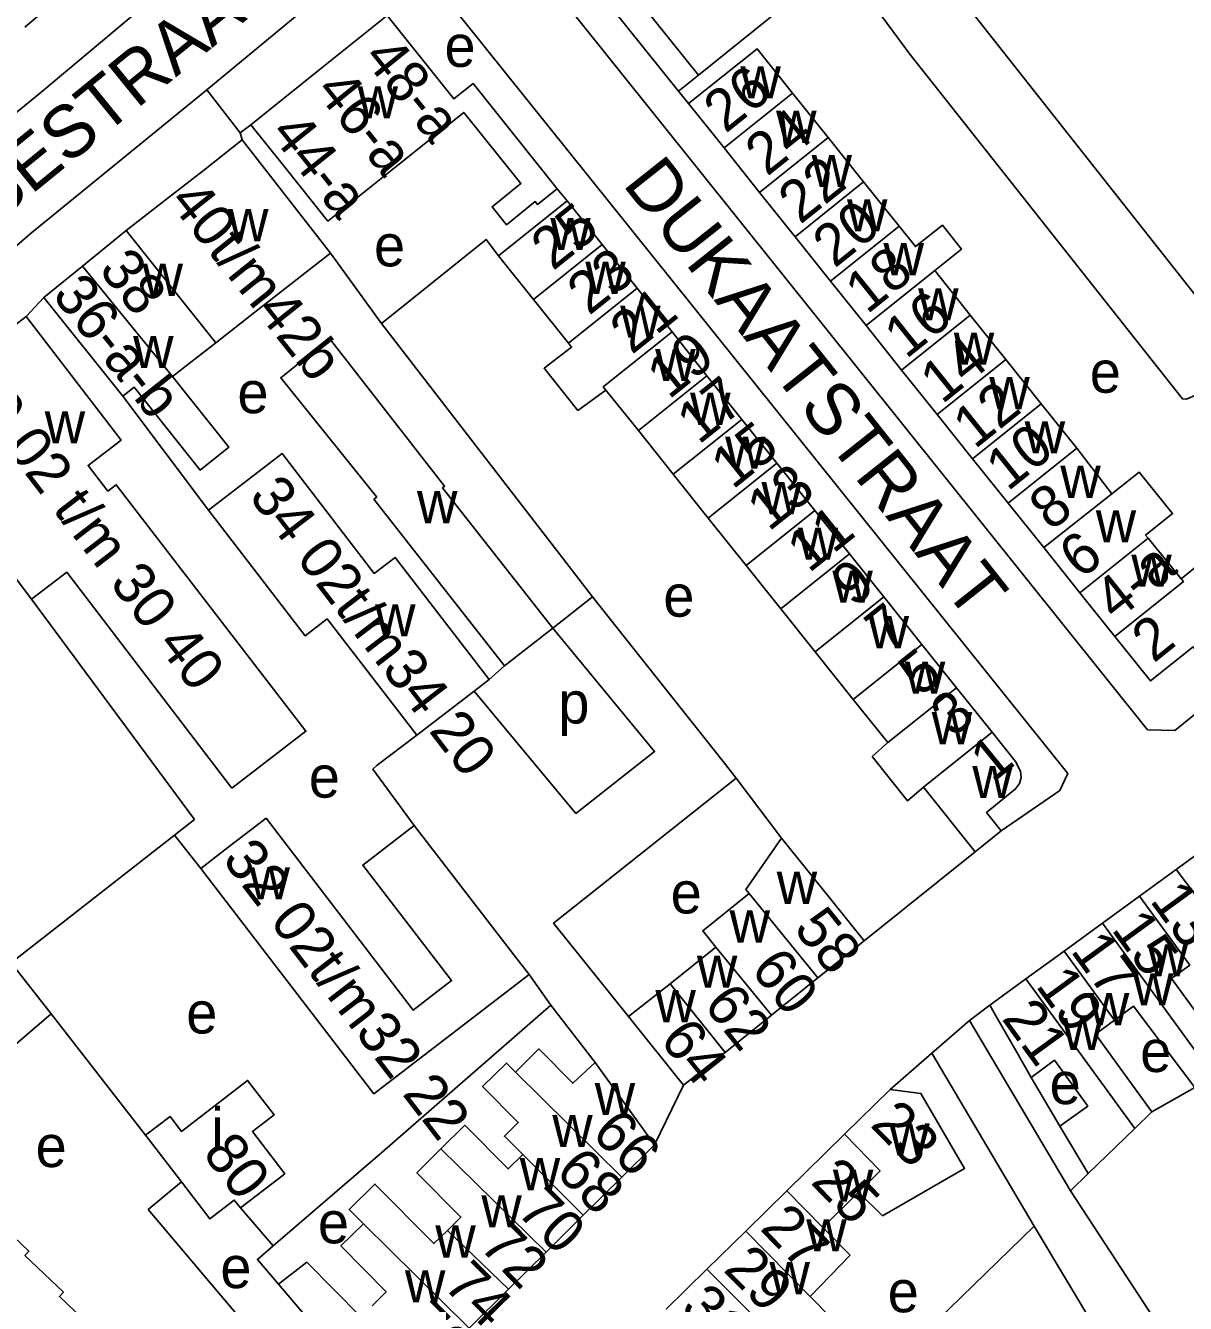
# Model space of a CAD drawing. Extents: x 161141 to 163125, y 381621 to 383200.
# Drawn here: x 162034.5 to 162145.3, y 382848.2 to 382970.4 of the extents above; entities that cross this region are included whole.
import ezdxf

# ---------------------------------------------------------------- set-up
doc = ezdxf.new("R2010")
doc.units = 0
for name, color, linetype in [('BLT_Basislijn', 7, 'Continuous'), ('BLT_Bebouwing', 7, 'Continuous'), ('BLT_Centroide', 7, 'Continuous'), ('BLT_Huisnummer', 7, 'Continuous'), ('BLT_Huisnummer_ tussenligend', 7, 'Continuous'), ('BLT_Huisnummer_reeks', 7, 'Continuous'), ('BLT_Onderverdeling_panden', 7, 'Continuous'), ('BLT_Plantopo', 7, 'Continuous'), ('BLT_Straatnaam', 7, 'Continuous')]:
    doc.layers.add(name, color=color, linetype=linetype)

msp = doc.modelspace()

# ---------------------------------------------------------------- linework, layer by layer
at = {"layer": 'BLT_Basislijn'}
for p, q in [((162098.79, 382965.63), (162112.37, 382976.59)), ((162039.04, 382974.17), (162034.4, 382970.22)), ((162054.96, 382960.11), (162051.8, 382964.24)), ((162096.87, 382964.1), (162097.83, 382962.92)), ((162055.99, 382960.89), (162054.96, 382960.11)), ((162055.17, 382959.44), (162054.96, 382960.11)), ((162086.24, 382953.62), (162085.29, 382954.77)), ((162063.62, 382948.61), (162068.5, 382941.89)), ((162036.21, 382944.38), (162034.52, 382942.57)), ((162043.75, 382934.93), (162051.96, 382924.05)), ((162035.04, 382915.55), (162050.62, 382894.48)), ((162084.88, 382912.76), (162088.66, 382915.76)), ((162078.77, 382907.84), (162080.25, 382909.15)), ((162068.06, 382899.66), (162071.85, 382902.52)), ((162134.11, 382898.87), (162133.32, 382897.23)), ((162102.38, 382898.42), (162084.92, 382884.56)), ((162102.38, 382898.42), (162106.74, 382892.7)), ((162133.32, 382897.23), (162127.73, 382893.39)), ((162051.2, 382889.78), (162048.7, 382892.97)), ((162084.92, 382884.56), (162092.09, 382875.64)), ((162082.59, 382879.65), (162084.68, 382876.73)), ((162088.9, 382871.25), (162084.68, 382876.73)), ((162126.65, 382876.72), (162124.71, 382875.24)), ((162036.9, 382875.89), (162011.67, 382854.3)), ((162045.92, 382864.28), (162036.9, 382875.89)), ((162124.71, 382875.24), (162121.11, 382872.13)), ((162124.71, 382875.24), (162134.35, 382858.98)), ((162121.11, 382872.13), (162117.1, 382868.65)), ((162121.11, 382872.13), (162130.87, 382855.59)), ((162133.34, 382865.14), (162130.59, 382869.82)), ((162146.25, 382868.84), (162142.14, 382866.53)), ((162058.13, 382853.71), (162068.33, 382862.47)), ((162134.35, 382858.98), (162136.04, 382860.62)), ((162049.35, 382859.82), (162046.17, 382857.17)), ((162143.03, 382845.71), (162134.35, 382858.98)), ((162057.64, 382843.63), (162046.17, 382857.17)), ((162054.99, 382857.34), (162058.13, 382853.71)), ((162116.71, 382841.81), (162130.87, 382855.59)), ((162130.87, 382855.59), (162139.06, 382841.97))]:
    msp.add_line(p, q, dxfattribs=at)
for points in [[(162055.07, 383020.8), (162073.06, 382998.55), (162074.21, 382996.11), (162061.33, 382985.3), (162036.1, 382964.14), (162021.9, 382952.54)], [(162078.89, 382986.26), (162079.12, 382981.19), (162141.72, 382903.05), (162144.33, 382902.98), (162163.54, 382918.51)], [(162119.35, 382978.75), (162148.02, 382942.41), (162160.41, 382952.54)], [(162067.43, 382977.19), (162051.8, 382964.24)], [(162134.11, 382898.87), (162072.44, 382975.73), (162067.43, 382977.19)], [(162148.78, 382936.95), (162148.4, 382936.64), (162146.31, 382935.04), (162145.46, 382934.64), (162145.05, 382934.68), (162119.01, 382967.64), (162114.01, 382974.38)], [(162051.8, 382964.24), (162051.59, 382964.07), (162034.86, 382950.43), (162030.3, 382946.48), (162029.11, 382945.73), (162022.92, 382940.82), (162016.17, 382934.9), (162011.73, 382931.63), (162000.21, 382922), (161995.04, 382917.92), (161994.27, 382917.07), (161980.96, 382906.53), (161973.3, 382900), (161972.62, 382899.42), (161974.49, 382896.95)], [(162068.5, 382941.89), (162078.49, 382949.92), (162079.67, 382948.37)], [(162088.66, 382915.76), (162088.34, 382916.16), (162086.1, 382919.08), (162068.5, 382941.89)], [(162102.38, 382898.42), (162101.15, 382900), (162088.66, 382915.76)], [(162077.34, 382906.74), (162087.07, 382895.05), (162094.6, 382900.97), (162084.88, 382912.76)], [(162071.61, 382893.9), (162067.65, 382899.28), (162068.06, 382899.66)], [(162048.7, 382892.97), (162050.62, 382894.48)], [(162036.9, 382875.89), (162033.07, 382880.77), (162048.7, 382892.97)], [(162068.33, 382862.47), (162068.56, 382862.67), (162084.68, 382876.73)], [(162094.57, 382863.38), (162097.36, 382869.08)], [(162058.65, 382850.06), (162056.62, 382852.41), (162058.13, 382853.71)]]:
    msp.add_lwpolyline(points, dxfattribs=at)
at = {"layer": 'BLT_Bebouwing'}
for p, q in [((162111.18, 382959.67), (162107.79, 382963.92)), ((162114.58, 382955.43), (162111.18, 382959.67)), ((162104.62, 382954.42), (162101.23, 382958.67)), ((162117.98, 382951.18), (162114.58, 382955.43)), ((162044.07, 382950.78), (162047.52, 382953.47)), ((162086.24, 382953.62), (162079.67, 382948.37)), ((162089.58, 382949.44), (162086.24, 382953.62)), ((162108.02, 382950.18), (162104.62, 382954.42)), ((162039.89, 382947.37), (162044.07, 382950.78)), ((162111.42, 382945.93), (162108.02, 382950.18)), ((162092.92, 382945.26), (162089.58, 382949.44)), ((162036.21, 382944.38), (162039.89, 382947.37)), ((162083.01, 382944.19), (162079.67, 382948.37)), ((162124.77, 382942.69), (162121.37, 382946.94)), ((162096.26, 382941.08), (162092.92, 382945.26)), ((162114.81, 382941.69), (162111.42, 382945.93)), ((162043.75, 382934.93), (162036.21, 382944.38)), ((162086.35, 382940.01), (162083.01, 382944.19)), ((162024.72, 382935.01), (162034.52, 382942.57)), ((162128.17, 382938.45), (162124.77, 382942.69)), ((162118.21, 382937.44), (162114.81, 382941.69)), ((162099.6, 382936.9), (162096.26, 382941.08)), ((162131.56, 382934.2), (162128.17, 382938.45)), ((162102.95, 382932.72), (162099.6, 382936.9)), ((162121.61, 382933.2), (162118.21, 382937.44)), ((162093.04, 382931.65), (162089.93, 382935.52)), ((162134.96, 382929.96), (162131.56, 382934.2)), ((162106.29, 382928.54), (162102.95, 382932.72)), ((162125, 382928.95), (162121.61, 382933.2)), ((162096.38, 382927.47), (162093.04, 382931.65)), ((162138.32, 382925.61), (162134.96, 382929.96)), ((162109.91, 382924.01), (162106.29, 382928.54)), ((162128.4, 382924.71), (162125, 382928.95)), ((162099.72, 382923.29), (162096.38, 382927.47)), ((162067.76, 382925.08), (162080.25, 382909.15)), ((162131.8, 382920.46), (162128.4, 382924.71)), ((162103.34, 382918.76), (162099.72, 382923.29)), ((162113.22, 382919.88), (162109.91, 382924.01)), ((162135.25, 382916.15), (162131.8, 382920.46)), ((162144.94, 382917.48), (162141.77, 382921.36)), ((162116.51, 382915.76), (162113.22, 382919.88)), ((162106.65, 382914.62), (162103.34, 382918.76)), ((162033.36, 382917.72), (162035.04, 382915.55)), ((162120.15, 382911.2), (162116.51, 382915.76)), ((162138.59, 382911.97), (162135.25, 382916.15)), ((162109.95, 382910.5), (162106.65, 382914.62)), ((162123.46, 382907.07), (162120.15, 382911.2)), ((162113.59, 382905.95), (162109.95, 382910.5)), ((162077.34, 382906.74), (162078.77, 382907.84)), ((162126.87, 382902.81), (162123.46, 382907.07)), ((162071.85, 382902.52), (162077.34, 382906.74)), ((162116.89, 382901.82), (162113.59, 382905.95)), ((162115.4, 382900.49), (162116.89, 382901.82)), ((162125.25, 382891.39), (162120.3, 382897.56)), ((162081.13, 382881.54), (162071.61, 382893.9)), ((162125.25, 382891.39), (162127.73, 382893.39)), ((162148.2, 382892.43), (162144.46, 382889.7)), ((162053.39, 382891.47), (162051.2, 382889.78)), ((162114.64, 382882.88), (162125.25, 382891.39)), ((162144.46, 382889.7), (162140.94, 382887.14)), ((162140.94, 382887.14), (162137.4, 382884.56)), ((162137.4, 382884.56), (162133.74, 382881.89)), ((162114.64, 382882.88), (162110.21, 382879.32)), ((162082.59, 382879.65), (162081.13, 382881.54)), ((162100.44, 382882.28), (162096.07, 382878.77)), ((162133.74, 382881.89), (162130.09, 382879.23)), ((162110.21, 382879.32), (162105.77, 382875.76)), ((162096.07, 382878.77), (162092.09, 382875.64)), ((162105.77, 382875.76), (162101.34, 382872.21)), ((162101.34, 382872.21), (162097.36, 382869.08)), ((162117.1, 382868.65), (162112.76, 382864.4)), ((162142.14, 382866.53), (162140.5, 382864.94)), ((162112.76, 382864.4), (162107.23, 382858.98)), ((162091.46, 382860.29), (162094.57, 382863.38)), ((162087.76, 382856.63), (162091.46, 382860.29)), ((162107.23, 382858.98), (162103.32, 382855.12)), ((162110.67, 382855.48), (162114.09, 382858.84)), ((162084.22, 382853.12), (162087.76, 382856.63)), ((162103.32, 382855.12), (162099.59, 382851.47)), ((162080.64, 382849.58), (162084.22, 382853.12)), ((162099.59, 382851.47), (162095.7, 382847.65)), ((162076.86, 382845.83), (162080.64, 382849.58))]:
    msp.add_line(p, q, dxfattribs=at)
for points in [[(162090.84, 382988.77), (162084.33, 382983.57), (162090.64, 382975.62), (162088.83, 382974.16), (162096.87, 382964.1)], [(162098.2, 382979.54), (162091.76, 382974.41), (162098.79, 382965.63)], [(162085.29, 382954.77), (162077.24, 382964.82), (162075.4, 382963.38), (162069.02, 382971.32), (162062.5, 382966.11)], [(162097.83, 382962.92), (162104.39, 382968.16), (162107.79, 382963.92)], [(162062.5, 382966.11), (162055.99, 382960.89)], [(162096.87, 382964.1), (162098.79, 382965.63)], [(162085.29, 382954.77), (162083.41, 382953.26), (162083.19, 382953.54), (162080.43, 382951.33), (162079.05, 382953.05), (162081.81, 382955.26), (162076.35, 382962.07), (162069.88, 382956.89)], [(162101.23, 382958.67), (162097.83, 382962.92)], [(162055.99, 382960.89), (162059.12, 382956.99), (162063.37, 382951.68), (162069.88, 382956.89)], [(162047.52, 382953.47), (162051.46, 382956.51), (162055.17, 382959.44)], [(162055.17, 382959.44), (162063.62, 382948.61)], [(162121.37, 382946.94), (162123.95, 382949), (162122.11, 382951.3), (162119.53, 382949.24), (162117.98, 382951.18)], [(162056.1, 382942.74), (162063.62, 382948.61)], [(162034.52, 382942.57), (162043.59, 382930.74), (162040.44, 382928.32), (162042.33, 382925.86), (162043.12, 382926.47), (162061.26, 382902.9), (162054.18, 382897.48), (162038.39, 382918.11), (162035.04, 382915.55)], [(162052.64, 382940.04), (162056.1, 382942.74)], [(162048.51, 382936.82), (162050.4, 382938.3), (162052.64, 382940.04)], [(162084.88, 382912.76), (162074.33, 382926.18), (162074.52, 382926.33), (162063.52, 382940.46), (162058.85, 382936.7), (162068.03, 382925.29), (162067.76, 382925.08)], [(162089.93, 382935.52), (162087.26, 382933.58), (162084.03, 382937.61), (162086.65, 382939.62), (162086.35, 382940.01)], [(162048.51, 382936.82), (162053.9, 382930.08), (162051.14, 382927.88), (162044.83, 382935.79), (162043.75, 382934.93)], [(162051.96, 382924.05), (162058.99, 382929.46), (162067.79, 382918), (162069.78, 382919.53), (162078.77, 382907.84)], [(162141.77, 382921.36), (162141.53, 382921.66), (162144.11, 382923.72), (162140.91, 382927.68), (162138.32, 382925.61)], [(162051.96, 382924.05), (162061.18, 382912.04), (162063.28, 382913.65), (162071.85, 382902.52)], [(162151.55, 382912.48), (162146.48, 382918.73), (162144.94, 382917.48)], [(162080.25, 382909.15), (162084.88, 382912.76)], [(162151.55, 382912.48), (162147.49, 382909.24), (162146.07, 382910.99), (162141.99, 382907.72), (162138.59, 382911.97)], [(162127.73, 382893.39), (162126.33, 382895.13), (162129.1, 382897.39), (162129.47, 382897.91), (162129.64, 382898.48), (162129.59, 382899.08), (162129.11, 382900), (162126.87, 382902.81)], [(162120.3, 382897.56), (162118.76, 382896.27), (162115.4, 382900.49)], [(162071.61, 382893.9), (162066.69, 382890.12), (162075.19, 382879.07), (162071.52, 382876.24), (162057.45, 382894.59), (162053.39, 382891.47)], [(162106.74, 382892.7), (162103.33, 382887.77), (162103.62, 382887.41)], [(162114.64, 382882.88), (162111.51, 382886.77), (162106.74, 382892.7)], [(162051.2, 382889.78), (162067.76, 382868.23), (162082.59, 382879.65)], [(162103.62, 382887.41), (162099.19, 382883.84), (162100.44, 382882.28)], [(162149.39, 382871.89), (162144.02, 382879.26), (162145.76, 382880.53)], [(162130.09, 382879.23), (162126.65, 382876.72), (162127.23, 382875.71)], [(162138.56, 382875.28), (162140.39, 382876.61), (162146.25, 382868.84)], [(162092.09, 382875.64), (162097.36, 382869.08)], [(162127.23, 382875.71), (162129.12, 382872.38), (162130.59, 382869.82)], [(162142.14, 382866.53), (162136.74, 382873.95), (162138.56, 382875.28)], [(162088.9, 382871.25), (162086.77, 382869.26), (162083.54, 382872.54), (162081.29, 382870.31)], [(162081.29, 382870.31), (162080.43, 382871.19), (162078.15, 382868.94), (162081.56, 382865.5), (162080.24, 382864.19), (162081.99, 382862.43)], [(162094.57, 382863.38), (162088.9, 382871.25)], [(162130.59, 382869.82), (162132.82, 382871.45), (162136, 382867.08), (162133.34, 382865.14)], [(162054.99, 382857.34), (162058.96, 382860.38), (162059.24, 382860.6), (162056.14, 382864.63), (162058.23, 382866.24), (162055.69, 382869.53), (162049.38, 382864.65), (162048.27, 382866.09), (162045.92, 382864.28)], [(162116.37, 382856.57), (162124.23, 382861.12), (162120.06, 382868.27), (162117.1, 382868.65)], [(162045.92, 382864.28), (162046.26, 382863.83), (162049.35, 382859.82)], [(162081.99, 382862.43), (162080.6, 382861.06), (162076.46, 382865.24), (162074.17, 382862.97)], [(162136.04, 382860.62), (162133.34, 382865.14)], [(162140.5, 382864.94), (162136.04, 382860.62)], [(162074.17, 382862.97), (162071.87, 382860.7), (162076.07, 382856.46), (162074.79, 382855.19)], [(162049.35, 382859.82), (162052.06, 382856.29), (162054.41, 382858.09), (162054.99, 382857.34)], [(162074.79, 382855.19), (162073.5, 382853.92), (162067.86, 382859.62), (162065.4, 382857.19), (162066.75, 382855.82)], [(162114.09, 382858.84), (162116.37, 382856.57)], [(162066.75, 382855.82), (162064.6, 382853.7), (162068.92, 382849.32), (162067.58, 382847.99)], [(162109.46, 382848.87), (162113.29, 382852.81), (162110.67, 382855.48)], [(162066.5, 382846.93), (162061.34, 382852.15), (162058.65, 382850.06)], [(162058.65, 382850.06), (162063.67, 382844.12), (162062.78, 382843.24), (162067.09, 382838.18), (162069.12, 382838.17)], [(162110.34, 382844.31), (162111.55, 382843.08), (162113.38, 382844.89), (162109.46, 382848.87)]]:
    msp.add_lwpolyline(points, dxfattribs=at)
at = {"layer": 'BLT_Onderverdeling_panden'}
for p, q in [((162101.23, 382958.67), (162107.79, 382963.92)), ((162104.62, 382954.42), (162111.18, 382959.67)), ((162108.02, 382950.18), (162114.58, 382955.43)), ((162111.42, 382945.93), (162117.98, 382951.18)), ((162052.64, 382940.04), (162044.07, 382950.78)), ((162083.01, 382944.19), (162089.58, 382949.44)), ((162048.51, 382936.82), (162039.89, 382947.37)), ((162114.81, 382941.69), (162121.37, 382946.94)), ((162086.35, 382940.01), (162092.92, 382945.26)), ((162118.21, 382937.44), (162124.77, 382942.69)), ((162121.61, 382933.2), (162128.17, 382938.45)), ((162093.04, 382931.65), (162099.6, 382936.9)), ((162125, 382928.95), (162131.56, 382934.2)), ((162096.38, 382927.47), (162102.95, 382932.72)), ((162128.4, 382924.71), (162134.96, 382929.96)), ((162099.72, 382923.29), (162106.29, 382928.54)), ((162131.8, 382920.46), (162138.32, 382925.61)), ((162103.34, 382918.76), (162109.91, 382924.01)), ((162135.25, 382916.15), (162141.77, 382921.36)), ((162106.65, 382914.62), (162113.22, 382919.88)), ((162109.95, 382910.5), (162116.51, 382915.76)), ((162113.59, 382905.95), (162120.15, 382911.2)), ((162116.89, 382901.82), (162123.46, 382907.07)), ((162126.87, 382902.81), (162120.3, 382897.56)), ((162152.57, 382878.9), (162144.46, 382889.7)), ((162110.21, 382879.32), (162103.62, 382887.41)), ((162145.76, 382880.53), (162140.94, 382887.14)), ((162147.77, 382870.32), (162137.4, 382884.56)), ((162105.77, 382875.76), (162100.44, 382882.28)), ((162138.56, 382875.28), (162133.74, 382881.89)), ((162140.5, 382864.94), (162130.09, 382879.23)), ((162096.07, 382878.77), (162101.34, 382872.21)), ((162081.29, 382870.31), (162091.46, 382860.29)), ((162074.17, 382862.97), (162084.22, 382853.12)), ((162081.99, 382862.43), (162087.76, 382856.63)), ((162110.67, 382855.48), (162107.23, 382858.98)), ((162066.75, 382855.82), (162076.86, 382845.83)), ((162074.79, 382855.19), (162080.64, 382849.58)), ((162109.46, 382848.87), (162103.32, 382855.12)), ((162108.5, 382842.6), (162099.59, 382851.47))]:
    msp.add_line(p, q, dxfattribs=at)
for points in [[(162089.93, 382935.52), (162089.69, 382935.83), (162096.26, 382941.08)], [(162138.59, 382911.97), (162145.15, 382917.22), (162144.94, 382917.48)], [(162114.09, 382858.84), (162116.15, 382860.87), (162112.76, 382864.4)]]:
    msp.add_lwpolyline(points, dxfattribs=at)
at = {"layer": 'BLT_Plantopo'}
msp.add_lwpolyline([(162021.72, 382847.94), (162018.1, 382851.46), (162014.52, 382847.57), (162009.98, 382852.51), (162023.22, 382864.65), (162027.18, 382860.7), (162027.47, 382860.94), (162031.61, 382857.01), (162031.2, 382856.58), (162034.77, 382853.19), (162034.39, 382852.78), (162038.08, 382849.28), (162037.69, 382848.87), (162041.31, 382845.43)], dxfattribs=at)

# ---------------------------------------------------------------- texts
at = {"layer": 'BLT_Centroide'}
for s, p in [('e', (162074.51, 382966.42)), ('w', (162102.8, 382963.41)), ('w', (162066.2, 382961.5)), ('w', (162106.21, 382959.16)), ('w', (162109.6, 382954.94)), ('w', (162112.99, 382950.69)), ('w', (162053.81, 382949.75)), ('w', (162084.62, 382948.91)), ('e', (162067.77, 382947.35)), ('w', (162116.48, 382946.5)), ('w', (162045.64, 382944.53)), ('w', (162087.97, 382944.72)), ('w', (162119.79, 382942.19)), ('w', (162091.3, 382940.53)), ('w', (162044.74, 382937.62)), ('w', (162123.2, 382937.94)), ('w', (162094.65, 382936.38)), ('e', (162136.2, 382935.27)), ('e', (162054.71, 382933.31)), ('w', (162126.59, 382933.69)), ('w', (162097.99, 382932.19)), ('w', (162036.29, 382930.42)), ('w', (162129.98, 382929.47)), ('w', (162101.34, 382928)), ('w', (162133.38, 382925.22)), ('w', (162104.81, 382923.66)), ('w', (162071.88, 382922.8)), ('w', (162136.77, 382920.97)), ('w', (162108.28, 382919.31)), ('w', (162140.17, 382916.72)), ('w', (162111.59, 382915.19)), ('e', (162095.43, 382913.86)), ('w', (162067.87, 382911.97)), ('w', (162115.05, 382910.84)), ('w', (162118.52, 382906.5)), ('p', (162085.39, 382903.65)), ('w', (162121.09, 382901.66)), ('e', (162061.54, 382896.56)), ('w', (162124.97, 382896.52)), ('w', (162055.87, 382886.83)), ('w', (162106.27, 382886.4)), ('e', (162096.13, 382885.49)), ('w', (162101.76, 382882.7)), ('w', (162098.64, 382878.38)), ('w', (162141.72, 382879.48)), ('w', (162140.33, 382876.69)), ('w', (162094.67, 382875.09)), ('w', (162136.11, 382874.8)), ('e', (162049.82, 382874.01)), ('w', (162133.58, 382872.42)), ('e', (162141.02, 382870.33)), ('e', (162132.36, 382867.26)), ('w', (162088.87, 382866.22)), ('i', (162052.22, 382862.91)), ('w', (162084.81, 382863.16)), ('e', (162035.42, 382861.24)), ('w', (162117.03, 382862.34)), ('w', (162081.7, 382859.03)), ('w', (162111.64, 382857.92)), ('w', (162078.03, 382855.48)), ('e', (162062.41, 382853.95)), ('w', (162109.09, 382853.17)), ('w', (162073.63, 382852.59)), ('e', (162053.08, 382849.67)), ('w', (162105.58, 382849.09)), ('w', (162070.73, 382848.3)), ('e', (162116.88, 382847.36))]:
    msp.add_text(s, height=4, dxfattribs=at).set_placement(p)
at = {"layer": 'BLT_Huisnummer'}
for s, rotation, p in [('24', 38.663, (162105.34, 382955.89)), ('25', 38.647, (162084.87, 382946.86)), ('20', 38.6619, (162111.8, 382947.12)), ('21', 38.647, (162092.41, 382938.85)), ('16', 38.6619, (162118.63, 382938.43)), ('17', 38.647, (162098.81, 382930.24)), ('12', 38.6609, (162125.2, 382929.81)), ('13', 38.647, (162105.51, 382921.93)), ('8', 38.6598, (162132.49, 382921.97)), ('9', 38.647, (162113.59, 382914.69)), ('5', 38.647, (162119.99, 382906.13)), ('1', 39.142, (162126.9, 382897.9)), ('58', 308.731, (162107.79, 382884.01)), ('15', 306.0706, (162138.19, 382883.96)), ('21', 306.0681, (162127.71, 382875.43)), ('64', 308.7815, (162094.99, 382873.37)), ('23', 314.5128, (162115.11, 382865.21)), ('66', 314.6726, (162088.45, 382864.32)), ('80', 307.5596, (162051.29, 382862.53)), ('70', 314.6726, (162081.28, 382856.9)), ('27', 314.5064, (162104.57, 382855.31)), ('31', 314.5161, (162096.95, 382847.65)), ('76', 314.6726, (162070.37, 382846.05))]:
    msp.add_text(s, height=4, rotation=rotation, dxfattribs=at).set_placement(p)
at = {"layer": 'BLT_Huisnummer_ tussenligend'}
for s, rotation, p in [('26', 38.6587, (162101.37, 382960)), ('22', 38.663, (162108.51, 382951.3)), ('38', 308.6061, (162041.36, 382947)), ('23', 38.647, (162088.32, 382942.59)), ('18', 38.6619, (162114.9, 382942.71)), ('19', 38.647, (162095.95, 382934.56)), ('14', 38.6619, (162122.07, 382934.11)), ('15', 38.647, (162102.06, 382925.95)), ('10', 38.6609, (162128.35, 382925.78)), ('11', 38.647, (162109.34, 382917.96)), ('6', 38.6598, (162135.36, 382917.37)), ('7', 38.647, (162116.82, 382910.43)), ('2', 38.7095, (162142.3, 382909.36)), ('3', 39.142, (162123.11, 382902.21)), ('17', 306.0706, (162134.29, 382881.91)), ('60', 308.731, (162103.68, 382880.1)), ('19', 306.0681, (162130.95, 382878.58)), ('62', 308.731, (162099.18, 382876.72)), ('68', 314.6726, (162084.99, 382860.67)), ('25', 314.5128, (162109.42, 382859.73)), ('72', 314.6726, (162077.72, 382853.59)), ('29', 314.5064, (162101.08, 382851.36)), ('74', 314.6726, (162074.26, 382849.83))]:
    msp.add_text(s, height=4, rotation=rotation, dxfattribs=at).set_placement(p)
at = {"layer": 'BLT_Huisnummer_reeks'}
for s, rotation, p in [('48-a', 308.8478, (162066.62, 382967.26)), ('46-a', 308.6803, (162062.07, 382964.1)), ('44-a', 308.6782, (162057.74, 382960.03)), ('40t/m42b', 308.608, (162048.07, 382953.51)), ('36-a-b', 308.6006, (162036.91, 382944.57)), ('30 02 t/m 30 40', 307.5492, (162027.91, 382935.93)), ('34 02t/m34 20', 307.5492, (162055.72, 382925.35)), ('4-a', 38.7095, (162138.69, 382913.34)), ('32 02t/m32 22', 307.5492, (162053.18, 382890.63)), ('13-a', 306.0803, (162141.87, 382886.71))]:
    msp.add_text(s, height=4, rotation=rotation, dxfattribs=at).set_placement(p)
at = {"layer": 'BLT_Straatnaam'}
for s, rotation, p in [('SCHELLINGSTRAAT', 308.414, (162135.03, 383005.42)), ('TONGELRESESTRAAT', 39.114, (162002.98, 382928.13)), ('DUKAATSTRAAT', 308.414, (162091.45, 382955.2))]:
    msp.add_text(s, height=5, rotation=rotation, dxfattribs=at).set_placement(p)

doc.saveas('drawing.dxf')
